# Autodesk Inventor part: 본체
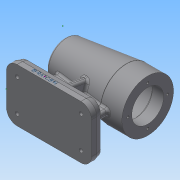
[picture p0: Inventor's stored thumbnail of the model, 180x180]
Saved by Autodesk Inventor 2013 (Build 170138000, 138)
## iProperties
Created: 2017-01
Part Number: 본체
Material: 일반
Document SubType Name: Modeling
Designer: Administrator
Density: 1 g/cm^3
Author: Administrator
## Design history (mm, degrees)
sketch "스케치2"
  geometry: L1 (0, 0)-(112, 0); L2 (112, 0)-(112, 34); L3 (112, 34)-(84.183, 34); L4 (83.818, 33.978)-(5.669, 24.382); A1 r 80 centre (80, 0) between (3.153, 22.238) and (0, 0); A2 r 3 centre (84.183, 31) between (84.183, 34) and (83.818, 33.978); A3 r 3 centre (6.035, 21.405) between (5.669, 24.382) and (3.153, 22.238); 2 further points
  constraints: 8 end point, 7 point on circle, 4 point on line, 4 tangent, 3 centre point, 2 perpendicular, 1 horizontal
  dimensions: "d2" = 112 distance of L1.start L1.end; "d3" = 28 distance of L2.end point (84, 34); "d4" = 7 deg angle of L3 L4; "d5" = 80 radius of A1; "d6" = 68 diameter of L3 L1; "d7" = 3 radius of A2; "d8" = 3 radius of A3
revolve "회전1" sketch "스케치2" stored, may be unused: angle "d9" = 90 deg
sketch "스케치3"
  geometry: L1 (0, 0)-(114.723, 0); L2 (6, 0)-(6, 7.5); L3 (9, 10.5)-(9, 10.5); L4 (9, 10.5)-(9, 15.7); L5 (9.3, 16)-(13, 16); L6 (13, 16)-(13, 17.2); L7 (13.3, 17.5)-(31, 17.5); L8 (31, 17.5)-(31, 20.7); L9 (31.3, 21)-(43, 21); L10 (43, 21)-(43, 21); L11 (46, 24)-(94, 24); L12 (97, 21)-(97, 21); L13 (97, 21)-(112, 21); L14 (112, -34)-(112, 34) reference; L15 (112, 21)-(112, 0); L16 (6, 0)-(112, 0); A1 r 3 centre (9, 7.5) between (9, 10.5) and (6, 7.5); A2 r 3 centre (46, 21) between (46, 24) and (43, 21); A3 r 3 centre (94, 21) between (97, 21) and (94, 24); A4 r 0.3 centre (9.3, 15.7) between (9.3, 16) and (9, 15.7); A5 r 0.3 centre (13.3, 17.2) between (13.3, 17.5) and (13, 17.2); A6 r 0.3 centre (31.3, 20.7) between (31.3, 21) and (31, 20.7); 4 further points
  constraints: 30 end point, 12 point on circle, 12 tangent, 10 parallel, 10 point on line, 6 centre point, 4 equal radius, 2 perpendicular, 1 collinear, 1 horizontal, 1 midpoint
  dimensions: "d10" = 15 distance from line of L14 L12.end; "d11" = 54 distance of L12.end L9.end; "d12" = 12 distance of point (31, 21) L9.end; "d13" = 18 distance of point (13, 17.5) L7.end; "d14" = 4 distance of point (9, 16) L5.end; "d15" = 3 distance of point (6, 10.5) L3.end; "d16" = 21 diameter of L3 L1; "d17" = 32 diameter of L5 L1; "d18" = 35 diameter of L7 L1; "d19" = 42 diameter of L9 L1; "d20" = 48 diameter of L11 L1; "d21" = 42 diameter of L13 L1; "d22" = 3 radius of A1; "d23" = 0.3 radius of A4
revolve "회전2" sketch "스케치3" stored, may be unused: angle "d24" = 90 deg
sketch "스케치4" dims "d26" = 52
  geometry: C1 r 21 at (0, 0) reference; C2 r 34 at (0, 0) reference; 3 further points
  constraints: 2 vertical alignment, 1 coincident, 2 other
hole "구멍1" sketch "스케치4" at (0, 26) diameter "d27" = 3.242; stored, may be unused: countersink angle "d31" = 90 deg, drill point angle "d33" = 118 deg; dims "d28" = 8, "d29" = 4, "d30" = 2, "d32" = 11
node "작업 평면1"
sketch "스케치5"
  geometry: 1 further point
sketch "스케치6"
  geometry: L1 (0, -35)-(-112, -35); L2 (-112, -35)-(-112, 35); L3 (-112, 35)-(0, 35); L4 (0, 35)-(0, -35); L5 (-112, 34)-(-112, -34) reference; L6 (-5.669, -24.382)-(-83.818, -33.978) reference; L7 (-5.669, 24.382)-(-83.818, 33.978) reference; 3 further points
  constraints: 8 end point, 2 midpoint, 2 parallel, 1 coincident, 1 horizontal, 1 perpendicular
  dimensions: "d38" = 112 distance of L2.end L3.end; "d39" = 70 distance of L1.end L2.end
extrude "돌출1" join sketch "스케치6" distance "d40" = 7; taper "d41" = 0 deg
fillet "모깎기1" dims "d42" = 14
sketch "스케치8"
  geometry: L1 (98, 35)-(14, 35) reference; L2 (0, 21)-(0, -21) reference; L3 (14, -35)-(98, -35) reference; L4 (112, -21)-(112, 21) reference; A1 r 14 centre (14, 21) between (14, 35) and (0, 21) reference; A2 r 14 centre (14, -21) between (0, -21) and (14, -35) reference; A3 r 14 centre (98, -21) between (98, -35) and (112, -21) reference; A4 r 14 centre (98, 21) between (112, 21) and (98, 35) reference; 1 further point
extrude "돌출2" join sketch "스케치8" distance "d43" = 7; taper "d44" = -15 deg
sketch "스케치11"
  geometry: L1 (18, 4)-(94, 4); L2 (94, 4)-(94, -4); L3 (94, -4)-(18, -4); L4 (18, -4)-(18, 4); L5 (18, 0)-(78.227, 0); L6 (98, -35)-(14, -35) reference; L7 (112, 21)-(112, -21) reference; L8 (0, -21)-(0, 21) reference; 1 further point
  constraints: 10 end point, 2 parallel, 1 horizontal, 1 midpoint, 1 perpendicular
  dimensions: "d49" = 8 distance between parallel lines of L3 L1; "d50" = 35 distance between parallel lines of L6 L5; "d52" = 18 distance between parallel lines of L4 L8; "d53" = 18 distance between parallel lines of L7 L2
extrude "돌출3" join sketch "스케치11" stored distance "d54" = 7; taper "d55" = 0 deg
node "작업 평면2"
sketch "스케치12"
  geometry: L1 (-67, 35)-(-60, 33.124) reference; L2 (-60, 33.124)-(-60, 4) reference; L3 (-60, 4)-(-30.299, 4) reference; L4 (-30.299, -4)-(-60, -4) reference; L5 (-60, -4)-(-60, -33.124) reference; L6 (-60, -33.124)-(-67, -35) reference; L7 (-67, -35)-(-74, -35) reference; L8 (-74, -35)-(-74, 35) reference; L9 (-74, 35)-(-67, 35) reference; L10 (-25.458, 16.909)-(-60, 23); L11 (-25.458, -16.909)-(-60, -23); C1 r 24 at (0, 0) reference; A1 r 30.562 centre (0, 0) between (-30.299, -4) and (-30.299, 4) reference; 1 further point
  constraints: 4 end point, 2 point on circle, 2 point on line
  dimensions: "d57" = 100 deg angle of L2 L10; "d58" = 12 distance from line of L10.end L9; "d59" = 100 deg angle of L5 L11; "d60" = 12 distance from line of L7 L11.end
  node "절단 모서리 투영1"
feature "리브1" dims "d61" = 1, "d62" = 8, "d63" = 0, "d64" = 0, "d65" = 1, "d66" = 1
feature "리브2" dims "d67" = 1, "d68" = 8, "d69" = 0, "d70" = 0, "d71" = 1, "d72" = 1
fillet "모깎기2" dims "d73" = 3
fillet "모깎기3" dims "d74" = 3
fillet "모깎기4" dims "d75" = 3
fillet "모깎기5" dims "d76" = 1
sketch "스케치15" dims "d77" = 10, "d78" = 10, "d84" = 10, "d88" = 10
  geometry: L1 (0, -21)-(0, 21) reference; L2 (112, 21)-(112, -21) reference; L3 (98, -35)-(14, -35) reference; L4 (14, 35)-(98, 35) reference; L5 (16.887, -16)-(19.774, -21); L6 (19.774, -21)-(16.887, -26); L7 (16.887, -26)-(11.113, -26); L8 (11.113, -26)-(8.226, -21); L9 (8.226, -21)-(11.113, -16); L10 (11.113, -16)-(16.887, -16); L11 (100.887, -16)-(103.774, -21); L12 (103.774, -21)-(100.887, -26); L13 (100.887, -26)-(95.113, -26); L14 (95.113, -26)-(92.226, -21); L15 (92.226, -21)-(95.113, -16); L16 (95.113, -16)-(100.887, -16); L17 (100.887, 26)-(103.774, 21); L18 (103.774, 21)-(100.887, 16); L19 (100.887, 16)-(95.113, 16); L20 (95.113, 16)-(92.226, 21); L21 (92.226, 21)-(95.113, 26); L22 (95.113, 26)-(100.887, 26); L23 (16.887, 26)-(19.774, 21); L24 (19.774, 21)-(16.887, 16); L25 (16.887, 16)-(11.113, 16); L26 (11.113, 16)-(8.226, 21); L27 (8.226, 21)-(11.113, 26); L28 (11.113, 26)-(16.887, 26); C1 r 2.5 at (14, -21); C2 r 2.5 at (98, -21); C3 r 2.5 at (98, 21); C4 r 2.5 at (14, 21); 13 further points
  constraints: 48 end point, 8 coincident, 4 centre point, 4 midpoint, 4 vertical alignment, 60 other
  dimensions: "d79" = 84 distance of point (98, -21) point (14, -21); "d82" = 14 distance from line of point (14, -21) L1; "d83" = 14 distance from line of L2 point (98, -21); "d85" = 42 distance of point (14, -21) point (14, 21); "d86" = 14 distance from line of L3 point (14, -21); "d87" = 14 distance from line of point (14, 21) L4; "d89" = 42 distance of point (98, -21) point (98, 21); "d90" = 14 distance from line of L4 point (98, 21); "d93" = 5 diameter of C1; "d94" = 5 diameter of C2; "d95" = 5 diameter of C3; "d96" = 5 diameter of C4
extrude "돌출4" cut sketch "스케치15" distance "d91" = 4; taper "d92" = 0 deg
extrude "돌출5" cut sketch "스케치15" stored distance "d97" = 4; taper "d98" = 0 deg
sketch "스케치17"
  geometry: 2 further points
  constraints: 1 other
node "솔리드1"
pattern_circular "원형 패턴1" dims angle "d35" = 360 deg
node "투영된 루프1"
other parameters: "d37" = -74, "d56" = 56
